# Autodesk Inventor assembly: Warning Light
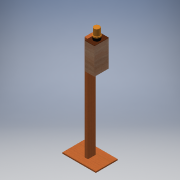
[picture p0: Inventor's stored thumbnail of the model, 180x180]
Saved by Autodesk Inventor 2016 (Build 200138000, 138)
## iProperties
Created: 2018-01
Part Number: Warning Light
Document SubType Name: Assembly
Designer: Student
Author: Student
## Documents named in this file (6)
- C:\Users\Student\Desktop\Warning Light.iam
- C:\Users\Student\Desktop\LightPost.ipt
- C:\Users\Student\Desktop\box.ipt
- C:\Users\Student\Desktop\Part6.ipt
- C:\Users\Student\Desktop\warningLightBase.ipt
- C:\Users\Student\Desktop\WarningLightTop.ipt
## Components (5 placed, 5 different names)
1. LightPost:1 — Flush:1, Flush:3, Flush:4
2. box:1 — Flush:1, Flush:3, Flush:4, Mate:1, Flush:5, Flush:6
3. Part6:1 — Mate:1, Flush:5, Flush:6, Flush:7, Flush:8
4. warningLightBase:1 — Flush:7, Flush:8, Flush:9, Flush:10
5. WarningLightTop:1 — Flush:9, Flush:10
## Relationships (10: Flush 9, Mate 1)
- Flush:1: LightPost:1 ↔ box:1
- Flush:3: LightPost:1 ↔ box:1
- Flush:4: LightPost:1 ↔ box:1
- Mate:1: box:1 ↔ Part6:1
- Flush:5: box:1 ↔ Part6:1
- Flush:6: box:1 ↔ Part6:1
- Flush:7: Part6:1 ↔ warningLightBase:1
- Flush:8: Part6:1 ↔ warningLightBase:1
- Flush:9: warningLightBase:1 ↔ WarningLightTop:1
- Flush:10: warningLightBase:1 ↔ WarningLightTop:1
